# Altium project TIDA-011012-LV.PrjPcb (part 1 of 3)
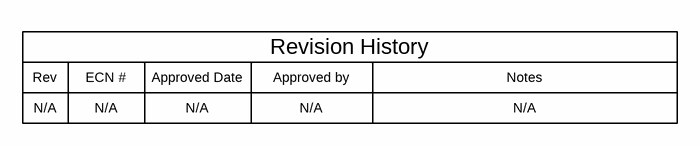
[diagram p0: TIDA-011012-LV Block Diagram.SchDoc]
CopyrightYear: 2026; EVM_orderable: NA; PCB_Rev: E1; PRJ_Customer: Public Release; PRJ_Engineer: A. Lechner, R. Ruffo; PRJ_Number: TIDA-011012-LV; PRJ_Title: Change in menu Project|Project Options|Parameters; SCH_Rev: E1; TechSupport: http://www.ti.com/support; TID: TIDA-011012-LV
10 sheets, 411 parts. Net scope: hierarchical (ports join the sheet entries above them; power ports are global).
Board file: TIDA-011012-LV.PcbDoc
Sheets:
  TIDA-011012-LV Block Diagram.SchDoc
  TIDA-011012-LV Power Conversion.SchDoc
    U_TIDA-011012 Fans and Temp Sense = TIDA-011012-LV Fans and Temp Sense.SchDoc
    U_TIDA-011012 Optical Interface = TIDA-011012-LV Optical Interface.SchDoc
    U_TIDA-011012 Communication = TIDA-011012-LV Communication.SchDoc
    U_TIDA-011012 DC IV Sensing = TIDA-011012-LV DC IV Sensing.SchDoc
    U_TIDA-011012 Current Comparator = TIDA-011012-LV Current Comparator.SchDoc
    U_TIDA-011012 Switch Node Hall Current Sensing = TIDA-011012-LV Switch Node Hall Current Sensing.SchDoc
    U_TIDA-011012 Auxiliary Power = TIDA-011012-LV  Auxiliary Power.SchDoc
    U_TIDA-011012_Hardware = TIDA-011012-LV Hardware.SchDoc

## Sheet TIDA-011012-LV Block Diagram.SchDoc
size 431 x 279 mm; Date: Not shown in title block; ApprovedBy: Not shown in title block; CheckedBy: Not shown in title block; Author: Not shown in title block; CompanyName: Not shown in title block; Engineer: Not shown in title block; Organization: Not shown in title block; Address1: Not shown in title block; Address2: Not shown in title block; Address3: Not shown in title block; Address4: Not shown in title block; DocumentNumber: 1; Revision: Use project parameter SCH_Rev; SheetNumber: 1; SheetTotal: 10; PageSetup: Record=PageOptions¦CenterHorizontal=True¦CenterVertical=True¦PrintScale=1.00¦XCorrection=1.00¦YCorrection=1.00¦PrintKind=0¦BorderSize=5000000¦LeftOffset=0¦BottomOffset=0¦Orientation=2¦PaperLength=1000¦PaperWidth=1000¦Scale=100¦PaperSource=15¦PrintQuality=600¦MediaType=1¦DitherType=10¦PaperKind=Letter¦PrintScaleMode=1

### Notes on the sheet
- Rev
- N/A
- ECN #
- Approved Date
- Approved by
- Revision History
- Notes

## Sheet TIDA-011012-LV Power Conversion.SchDoc
size 431 x 279 mm; Date: Not shown in title block; ApprovedBy: Not shown in title block; CheckedBy: Not shown in title block; Author: Not shown in title block; CompanyName: Not shown in title block; Engineer: Not shown in title block; Organization: Not shown in title block; Address1: Not shown in title block; Address2: Not shown in title block; Address3: Not shown in title block; Address4: Not shown in title block; DocumentNumber: 2; Revision: Use project parameter SCH_Rev; SheetNumber: 2; SheetTotal: 10; PageSetup: Record=PageOptions¦CenterHorizontal=True¦CenterVertical=True¦PrintScale=1.00¦XCorrection=1.00¦YCorrection=1.00¦PrintKind=0¦BorderSize=5000000¦LeftOffset=0¦BottomOffset=0¦Orientation=2¦PaperLength=1000¦PaperWidth=1000¦Scale=100¦PaperSource=15¦PrintQuality=600¦MediaType=1¦DitherType=10¦PaperKind=Letter¦PrintScaleMode=1
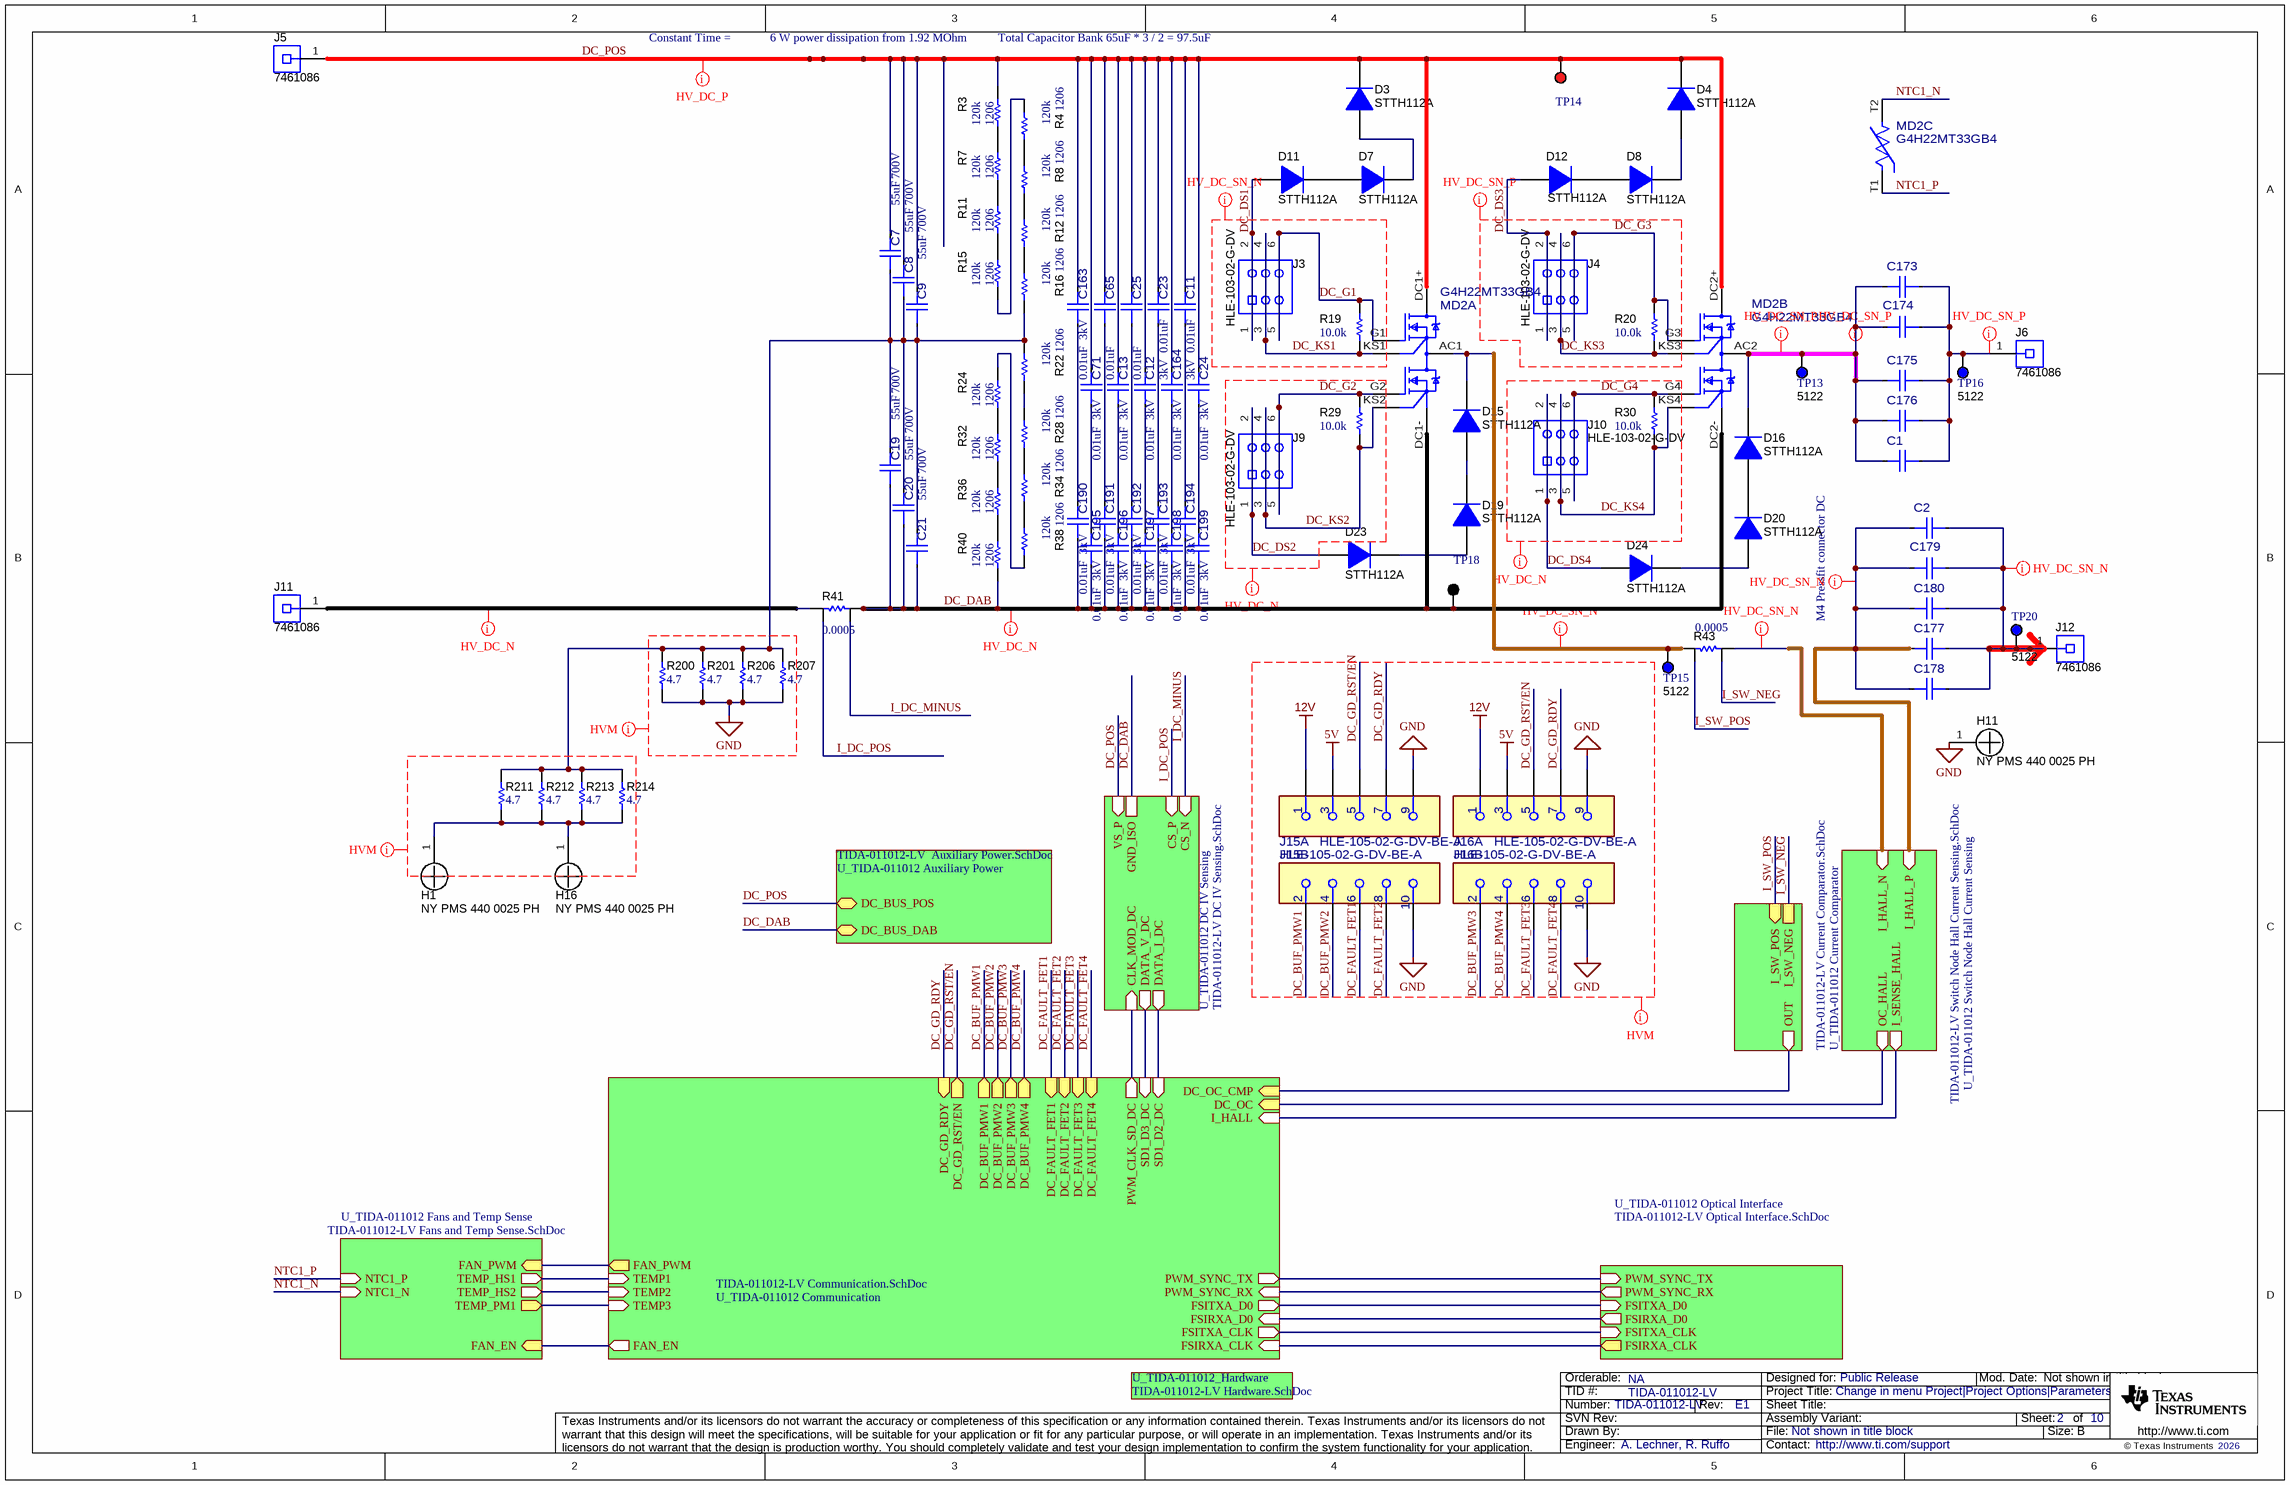
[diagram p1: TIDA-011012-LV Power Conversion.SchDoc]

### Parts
C1  C4ASMBW4200A3HJ  [FP-C4ASMBW4200A3HJ_RADIAL-MFG]  (value not drawn)
C2  C4ASMBW4200A3HJ  [FP-C4ASMBW4200A3HJ_RADIAL-MFG]  (value not drawn)
C7  ValueDisplayed: 55uF  VDC_V: 700V  [FP-C4AQJBW5550M3MJ_PTH_CAP_57MM5_30MM0-MFG]  (hidden comment: C4AQJBW5550M3MJ)
C8  ValueDisplayed: 55uF  VDC_V: 700V  [FP-C4AQJBW5550M3MJ_PTH_CAP_57MM5_30MM0-MFG]  (hidden comment: C4AQJBW5550M3MJ)
C9  ValueDisplayed: 55uF  VDC_V: 700V  [FP-C4AQJBW5550M3MJ_PTH_CAP_57MM5_30MM0-MFG]  (hidden comment: C4AQJBW5550M3MJ)
C11  ValueDisplayed: 0.01uF  VDC_V: 3kV  [FP-C2220X103KHRAC7800_2220-MFG]  (hidden comment: C2220X103KHRAC7800)
C12  ValueDisplayed: 0.01uF  VDC_V: 3kV  [FP-C2220X103KHRAC7800_2220-MFG]  (hidden comment: C2220X103KHRAC7800)
C13  ValueDisplayed: 0.01uF  VDC_V: 3kV  [FP-C2220X103KHRAC7800_2220-MFG]  (hidden comment: C2220X103KHRAC7800)
C19  ValueDisplayed: 55uF  VDC_V: 700V  [FP-C4AQJBW5550M3MJ_PTH_CAP_57MM5_30MM0-MFG]  (hidden comment: C4AQJBW5550M3MJ)
C20  ValueDisplayed: 55uF  VDC_V: 700V  [FP-C4AQJBW5550M3MJ_PTH_CAP_57MM5_30MM0-MFG]  (hidden comment: C4AQJBW5550M3MJ)
C21  ValueDisplayed: 55uF  VDC_V: 700V  [FP-C4AQJBW5550M3MJ_PTH_CAP_57MM5_30MM0-MFG]  (hidden comment: C4AQJBW5550M3MJ)
C23  ValueDisplayed: 0.01uF  VDC_V: 3kV  [FP-C2220X103KHRAC7800_2220-MFG]  (hidden comment: C2220X103KHRAC7800)
C24  ValueDisplayed: 0.01uF  VDC_V: 3kV  [FP-C2220X103KHRAC7800_2220-MFG]  (hidden comment: C2220X103KHRAC7800)
C25  ValueDisplayed: 0.01uF  [FP-C2220X103KHRAC7800_2220-MFG]  (hidden comment: C2220X103KHRAC7800)
C65  ValueDisplayed: 0.01uF  [FP-C2220X103KHRAC7800_2220-MFG]  (hidden comment: C2220X103KHRAC7800)
C71  ValueDisplayed: 0.01uF  VDC_V: 3kV  [FP-C2220X103KHRAC7800_2220-MFG]  (hidden comment: C2220X103KHRAC7800)
C163  ValueDisplayed: 0.01uF  VDC_V: 3kV  [FP-C2220X103KHRAC7800_2220-MFG]  (hidden comment: C2220X103KHRAC7800)
C164  ValueDisplayed: 0.01uF  VDC_V: 3kV  [FP-C2220X103KHRAC7800_2220-MFG]  (hidden comment: C2220X103KHRAC7800)
C173  C4ASMBW4200A3HJ  [FP-C4ASMBW4200A3HJ_RADIAL-MFG]  (value not drawn)
C174  C4ASMBW4200A3HJ  [FP-C4ASMBW4200A3HJ_RADIAL-MFG]  (value not drawn)
C175  C4ASMBW4200A3HJ  [FP-C4ASMBW4200A3HJ_RADIAL-MFG]  (value not drawn)
C176  C4ASMBW4200A3HJ  [FP-C4ASMBW4200A3HJ_RADIAL-MFG]  (value not drawn)
C177  C4ASMBW4200A3HJ  [FP-C4ASMBW4200A3HJ_RADIAL-MFG]  (value not drawn)
C178  C4ASMBW4200A3HJ  [FP-C4ASMBW4200A3HJ_RADIAL-MFG]  (value not drawn)
C179  C4ASMBW4200A3HJ  [FP-C4ASMBW4200A3HJ_RADIAL-MFG]  (value not drawn)
C180  C4ASMBW4200A3HJ  [FP-C4ASMBW4200A3HJ_RADIAL-MFG]  (value not drawn)
C190  ValueDisplayed: 0.01uF  VDC_V: 3kV  [FP-C2220X103KHRAC7800_2220-MFG]  (hidden comment: C2220X103KHRAC7800)
C191  ValueDisplayed: 0.01uF  VDC_V: 3kV  [FP-C2220X103KHRAC7800_2220-MFG]  (hidden comment: C2220X103KHRAC7800)
C192  ValueDisplayed: 0.01uF  VDC_V: 3kV  [FP-C2220X103KHRAC7800_2220-MFG]  (hidden comment: C2220X103KHRAC7800)
C193  ValueDisplayed: 0.01uF  VDC_V: 3kV  [FP-C2220X103KHRAC7800_2220-MFG]  (hidden comment: C2220X103KHRAC7800)
C194  ValueDisplayed: 0.01uF  VDC_V: 3kV  [FP-C2220X103KHRAC7800_2220-MFG]  (hidden comment: C2220X103KHRAC7800)
C195  ValueDisplayed: 0.01uF  VDC_V: 3kV  [FP-C2220X103KHRAC7800_2220-MFG]  (hidden comment: C2220X103KHRAC7800)
C196  ValueDisplayed: 0.01uF  VDC_V: 3kV  [FP-C2220X103KHRAC7800_2220-MFG]  (hidden comment: C2220X103KHRAC7800)
C197  ValueDisplayed: 0.01uF  VDC_V: 3kV  [FP-C2220X103KHRAC7800_2220-MFG]  (hidden comment: C2220X103KHRAC7800)
C198  ValueDisplayed: 0.01uF  VDC_V: 3kV  [FP-C2220X103KHRAC7800_2220-MFG]  (hidden comment: C2220X103KHRAC7800)
C199  ValueDisplayed: 0.01uF  VDC_V: 3kV  [FP-C2220X103KHRAC7800_2220-MFG]  (hidden comment: C2220X103KHRAC7800)
D3  STTH112A  [SMA]
D4  STTH112A  [SMA]
D7  STTH112A  [SMA]
D8  STTH112A  [SMA]
D11  STTH112A  [SMA]
D12  STTH112A  [SMA]
D15  STTH112A  [SMA]
D16  STTH112A  [SMA]
D19  STTH112A  [SMA]
D20  STTH112A  [SMA]
D23  STTH112A  [SMA]
D24  STTH112A  [SMA]
H1  NY PMS 440 0025 PH  [NY PMS 440 0025 PH]
H11  NY PMS 440 0025 PH  [NY PMS 440 0025 PH]
H16  NY PMS 440 0025 PH  [NY PMS 440 0025 PH]
J3  HLE-103-02-G-DV  [Samtec_HLE-103-02-x-DV]
J4  HLE-103-02-G-DV  [Samtec_HLE-103-02-x-DV]
J5  7461086  [Wurth_7461086]
J6  7461086  [Wurth_7461086]
J9  HLE-103-02-G-DV  [Samtec_HLE-103-02-x-DV]
J10  HLE-103-02-G-DV  [Samtec_HLE-103-02-x-DV]
J11  7461086  [Wurth_7461086]
J12  7461086  [Wurth_7461086]
J15  HLE-105-02-G-DV-BE-A  [FP-HLE-105-02-G-DV-BE-A_CONN_RCPT_10-MFG]  (parts A,B of 2)
J16  HLE-105-02-G-DV-BE-A  [FP-HLE-105-02-G-DV-BE-A_CONN_RCPT_10-MFG]  (parts A,B of 2)
MD2  G4H22MT33GB4  [FP-G4H22MT33GB4_SiCPAK-G+_MODIFIED-MFG]  (parts A,B,C of 3)
R3  ValueDisplayed: 120k  [1206]  (hidden comment: RC1206FR-07120KL)
R4  ValueDisplayed: 120k  [1206]  (hidden comment: RC1206FR-07120KL)
R7  ValueDisplayed: 120k  [1206]  (hidden comment: RC1206FR-07120KL)
R8  ValueDisplayed: 120k  [1206]  (hidden comment: RC1206FR-07120KL)
R11  ValueDisplayed: 120k  [1206]  (hidden comment: RC1206FR-07120KL)
R12  ValueDisplayed: 120k  [1206]  (hidden comment: RC1206FR-07120KL)
R15  ValueDisplayed: 120k  [1206]  (hidden comment: RC1206FR-07120KL)
R16  ValueDisplayed: 120k  [1206]  (hidden comment: RC1206FR-07120KL)
R19  ValueDisplayed: 10.0k  [0603]  (hidden comment: ERJ-3EKF1002V)
R20  ValueDisplayed: 10.0k  [0603]  (hidden comment: ERJ-3EKF1002V)
R22  ValueDisplayed: 120k  [1206]  (hidden comment: RC1206FR-07120KL)
R24  ValueDisplayed: 120k  [1206]  (hidden comment: RC1206FR-07120KL)
R28  ValueDisplayed: 120k  [1206]  (hidden comment: RC1206FR-07120KL)
R29  ValueDisplayed: 10.0k  [0603]  (hidden comment: ERJ-3EKF1002V)
R30  ValueDisplayed: 10.0k  [0603]  (hidden comment: ERJ-3EKF1002V)
R32  ValueDisplayed: 120k  [1206]  (hidden comment: RC1206FR-07120KL)
R34  ValueDisplayed: 120k  [1206]  (hidden comment: RC1206FR-07120KL)
R36  ValueDisplayed: 120k  [1206]  (hidden comment: RC1206FR-07120KL)
R38  ValueDisplayed: 120k  [1206]  (hidden comment: RC1206FR-07120KL)
R40  ValueDisplayed: 120k  [1206]  (hidden comment: RC1206FR-07120KL)
R41  ValueDisplayed: 0.0005  [WSL4026_0p5milli]  (hidden comment: WSL4026L5000FEB)
R43  ValueDisplayed: 0.0005  [WSL4026_0p5milli]  (hidden comment: WSL4026L5000FEB)
R200  ValueDisplayed: 4.7  [1206]  (hidden comment: CRCW12064R70JNEA)
R201  ValueDisplayed: 4.7  [1206]  (hidden comment: CRCW12064R70JNEA)
R206  ValueDisplayed: 4.7  [1206]  (hidden comment: CRCW12064R70JNEA)
R207  ValueDisplayed: 4.7  [1206]  (hidden comment: CRCW12064R70JNEA)
R211  ValueDisplayed: 4.7  [1206]  (hidden comment: CRCW12064R70JNEA)
R212  ValueDisplayed: 4.7  [1206]  (hidden comment: CRCW12064R70JNEA)
R213  ValueDisplayed: 4.7  [1206]  (hidden comment: CRCW12064R70JNEA)
R214  ValueDisplayed: 4.7  [1206]  (hidden comment: CRCW12064R70JNEA)
TP13  5122  [Keystone5122]
TP14  5010  [Keystone5010]  (value not drawn)
TP15  5122  [Keystone5122]
TP16  5122  [Keystone5122]
TP18  5011  [Keystone5011]  (value not drawn)
TP20  5122  [Keystone5122]

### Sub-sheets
U_TIDA-011012 Auxiliary Power = TIDA-011012-LV  Auxiliary Power.SchDoc: DC_BUS_POS (bidir), DC_BUS_DAB (bidir)
U_TIDA-011012 Communication = TIDA-011012-LV Communication.SchDoc: SD1_D2_DC (in), SD1_D3_DC (in), FAN_EN (out), TEMP1 (in), TEMP2 (in), TEMP3 (in), FSITXA_D0 (out), PWM_SYNC_TX (out), PWM_SYNC_RX (in), I_HALL (in), PWM_CLK_SD_DC (out), DC_GD_RDY (in), DC_FAULT_FET1 (in), DC_OC (in), DC_OC_CMP (in), DC_BUF_PMW1 (out), DC_BUF_PMW2 (out), DC_BUF_PMW3 (out), DC_BUF_PMW4 (out), DC_FAULT_FET2 (in), DC_FAULT_FET3 (in), DC_FAULT_FET4 (in), DC_GD_RST/EN (out), FAN_PWM (out), FSIRXA_D0 (in), FSITXA_CLK (out), FSIRXA_CLK (in)
U_TIDA-011012 Current Comparator = TIDA-011012-LV Current Comparator.SchDoc: OUT (out), I_SW_NEG, I_SW_POS (in)
U_TIDA-011012 DC IV Sensing = TIDA-011012-LV DC IV Sensing.SchDoc: CS_P (in), CS_N (in), DATA_I_DC (out), GND_ISO, VS_P (in), DATA_V_DC (out), CLK_MOD_DC (in)
U_TIDA-011012 Fans and Temp Sense = TIDA-011012-LV Fans and Temp Sense.SchDoc: TEMP_HS1 (out), TEMP_HS2 (out), NTC1_P (in), NTC1_N (in), FAN_EN (in), FAN_PWM (in), TEMP_PM1 (out)
U_TIDA-011012 Optical Interface = TIDA-011012-LV Optical Interface.SchDoc: PWM_SYNC_RX (out), FSITXA_D0 (in), PWM_SYNC_TX (in), FSITXA_CLK (in), FSIRXA_D0 (out), FSIRXA_CLK (out)
U_TIDA-011012 Switch Node Hall Current Sensing = TIDA-011012-LV Switch Node Hall Current Sensing.SchDoc: I_HALL_P (in), I_HALL_N (in), I_SENSE_HALL (out), OC_HALL (out)
U_TIDA-011012_Hardware = TIDA-011012-LV Hardware.SchDoc: no entries

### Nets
5V: J15.3 J16.3
12V: J15.1 J16.1
GND: H11.1 J15.9 J15.10 J16.9 J16.10 R200.1 R201.1 R206.1 R207.1
CLK_MOD_DC: sheet U_TIDA-011012 Communication/PWM_CLK_SD_DC, sheet U_TIDA-011012 DC IV Sensing/CLK_MOD_DC
DATA_I_DC: sheet U_TIDA-011012 Communication/SD1_D2_DC, sheet U_TIDA-011012 DC IV Sensing/DATA_I_DC
DATA_V_DC: sheet U_TIDA-011012 Communication/SD1_D3_DC, sheet U_TIDA-011012 DC IV Sensing/DATA_V_DC
DC_BUF_PMW1: J15.2 ; sheet U_TIDA-011012 Communication/DC_BUF_PMW1
DC_BUF_PMW2: J15.4 ; sheet U_TIDA-011012 Communication/DC_BUF_PMW2
DC_BUF_PMW3: J16.2 ; sheet U_TIDA-011012 Communication/DC_BUF_PMW3
DC_BUF_PMW4: J16.4 ; sheet U_TIDA-011012 Communication/DC_BUF_PMW4
DC_DAB: C19.1 C20.1 C21.1 C190.1 C191.1 C192.1 C193.1 C194.1 C195.1 C196.1 C197.1 C198.1 C199.1 MD2.DC1- MD2.DC2- R40.1 R41.2 TP18.1 ; sheet U_TIDA-011012 DC IV Sensing/GND_ISO, sheet U_TIDA-011012 Auxiliary Power/DC_BUS_DAB
DC_DS1: D11.2(A) J3.1 J3.2
DC_DS2: D23.2(A) J9.1 J9.2
DC_DS3: D12.2(A) J4.1 J4.2
DC_DS4: D24.2(A) J10.1 J10.2
DC_FAULT_FET1: J15.6 ; sheet U_TIDA-011012 Communication/DC_FAULT_FET1
DC_FAULT_FET2: J15.8 ; sheet U_TIDA-011012 Communication/DC_FAULT_FET2
DC_FAULT_FET3: J16.6 ; sheet U_TIDA-011012 Communication/DC_FAULT_FET3
DC_FAULT_FET4: J16.8 ; sheet U_TIDA-011012 Communication/DC_FAULT_FET4
DC_G1: J3.5 J3.6 MD2.G1 R19.2
DC_G2: J9.5 J9.6 MD2.G2 R29.2
DC_G3: J4.5 J4.6 MD2.G3 R20.2
DC_G4: J10.5 J10.6 MD2.G4 R30.2
DC_GD_RDY: J15.7 J16.7 ; sheet U_TIDA-011012 Communication/DC_GD_RDY
DC_GD_RST/EN: J15.5 J16.5 ; sheet U_TIDA-011012 Communication/DC_GD_RST/EN
DC_KS1: J3.3 J3.4 MD2.KS1 R19.1
DC_KS2: J9.3 J9.4 MD2.KS2 R29.1
DC_KS3: J4.3 J4.4 MD2.KS3 R20.1
DC_KS4: J10.3 J10.4 MD2.KS4 R30.1
DC_OC: sheet U_TIDA-011012 Communication/DC_OC, sheet U_TIDA-011012 Switch Node Hall Current Sensing/OC_HALL
DC_OC_CMP: sheet U_TIDA-011012 Communication/DC_OC_CMP, sheet U_TIDA-011012 Current Comparator/OUT
DC_POS: C7.2 C8.2 C9.2 C11.2 C12.2 C13.2 C23.2 C24.2 C25.2 C65.2 C71.2 C163.2 C164.2 D3.1(K) D4.1(K) J5.1 MD2.DC1+ MD2.DC2+ R3.2 TP14.1 ; sheet U_TIDA-011012 DC IV Sensing/VS_P, sheet U_TIDA-011012 Auxiliary Power/DC_BUS_POS
FAN_EN: sheet U_TIDA-011012 Fans and Temp Sense/FAN_EN, sheet U_TIDA-011012 Communication/FAN_EN
FAN_PWM: sheet U_TIDA-011012 Fans and Temp Sense/FAN_PWM, sheet U_TIDA-011012 Communication/FAN_PWM
FSIRXA_CLK: sheet U_TIDA-011012 Optical Interface/FSIRXA_CLK, sheet U_TIDA-011012 Communication/FSIRXA_CLK
FSIRXA_D0: sheet U_TIDA-011012 Optical Interface/FSIRXA_D0, sheet U_TIDA-011012 Communication/FSIRXA_D0
FSITXA_CLK: sheet U_TIDA-011012 Optical Interface/FSITXA_CLK, sheet U_TIDA-011012 Communication/FSITXA_CLK
FSITXA_D0: sheet U_TIDA-011012 Optical Interface/FSITXA_D0, sheet U_TIDA-011012 Communication/FSITXA_D0
I_DC_MINUS: R41.4 ; sheet U_TIDA-011012 DC IV Sensing/CS_N
I_DC_POS: R41.3 ; sheet U_TIDA-011012 DC IV Sensing/CS_P
I_HALL: sheet U_TIDA-011012 Communication/I_HALL, sheet U_TIDA-011012 Switch Node Hall Current Sensing/I_SENSE_HALL
I_HALL_N: R43.2 ; sheet U_TIDA-011012 Switch Node Hall Current Sensing/I_HALL_N
I_HALL_P: C2.2 C177.2 C178.2 C179.2 C180.2 ; sheet U_TIDA-011012 Switch Node Hall Current Sensing/I_HALL_P
I_SW_NEG: R43.4 ; sheet U_TIDA-011012 Current Comparator/I_SW_NEG
I_SW_POS: R43.3 ; sheet U_TIDA-011012 Current Comparator/I_SW_POS
NTC1_N: MD2.T2 ; sheet U_TIDA-011012 Fans and Temp Sense/NTC1_N
NTC1_P: MD2.T1 ; sheet U_TIDA-011012 Fans and Temp Sense/NTC1_P
PWM_SYNC_RX: sheet U_TIDA-011012 Optical Interface/PWM_SYNC_RX, sheet U_TIDA-011012 Communication/PWM_SYNC_RX
PWM_SYNC_TX: sheet U_TIDA-011012 Optical Interface/PWM_SYNC_TX, sheet U_TIDA-011012 Communication/PWM_SYNC_TX
TEMP1: sheet U_TIDA-011012 Fans and Temp Sense/TEMP_HS1, sheet U_TIDA-011012 Communication/TEMP1
TEMP2: sheet U_TIDA-011012 Fans and Temp Sense/TEMP_HS2, sheet U_TIDA-011012 Communication/TEMP2
TEMP3: sheet U_TIDA-011012 Fans and Temp Sense/TEMP_PM1, sheet U_TIDA-011012 Communication/TEMP3
NetC1_1: C1.1 C173.1 C174.1 C175.1 C176.1 J6.1 TP16.1
NetC1_2: C1.2 C173.2 C174.2 C175.2 C176.2 D16.1(K) MD2.AC2 TP13.1
NetC2_1: C2.1 C177.1 C178.1 C179.1 C180.1 J12.1 TP20.1
NetC7_1: C7.1 C8.1 C9.1 C19.2 C20.2 C21.2 R16.2 R22.1 R200.2 R201.2 R206.2 R207.2 R211.2 R212.2 R213.2 R214.2
NetC11_1: C11.1 C194.2
NetC12_1: C12.1 C197.2
NetC13_1: C13.1 C196.2
NetC23_1: C23.1 C193.2
NetC24_1: C24.1 C199.2
NetC25_1: C25.1 C192.2
NetC65_1: C65.1 C191.2
NetC71_1: C71.1 C195.2
NetC163_1: C163.1 C190.2
NetC164_1: C164.1 C198.2
NetD3_2: D3.2(A) D7.1(K)
NetD4_2: D4.2(A) D8.1(K)
NetD7_2: D7.2(A) D11.1(K)
NetD8_2: D8.2(A) D12.1(K)
NetD15_1: D15.1(K) MD2.AC1 R43.1 TP15.1
NetD15_2: D15.2(A) D19.1(K)
NetD16_2: D16.2(A) D20.1(K)
NetD19_2: D19.2(A) D23.1(K)
NetD20_2: D20.2(A) D24.1(K)
NetH1_1: H1.1 H16.1 R211.1 R212.1 R213.1 R214.1
NetJ11_1: J11.1 R41.1
NetR3_1: R3.1 R7.2
NetR4_1: R4.1 R15.1
NetR4_2: R4.2 R8.1
NetR7_1: R7.1 R11.2
NetR8_2: R8.2 R12.1
NetR11_1: R11.1 R15.2
NetR12_2: R12.2 R16.1
NetR22_2: R22.2 R28.1
NetR24_1: R24.1 R32.2
NetR24_2: R24.2 R38.2
NetR28_2: R28.2 R34.1
NetR32_1: R32.1 R36.2
NetR34_2: R34.2 R38.1
NetR36_1: R36.1 R40.2

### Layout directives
net class HV_DC_N: DC_DAB, DC_DS2, DC_G2, DC_G4, DC_KS2, DC_KS4, NetJ11_1
net class HV_DC_SN_N: DC_DS1, DC_G1, DC_KS1, I_HALL_N, I_HALL_P, NetC2_1, NetD15_1
net class HV_DC_SN_P: DC_DS3, DC_G3, DC_KS3, NetC1_1, NetC1_2
net class HVM: 5V, 12V, (no net found under the mark), DC_BUF_PMW1, DC_BUF_PMW2, DC_BUF_PMW3, DC_BUF_PMW4, DC_FAULT_FET1, DC_FAULT_FET2, DC_FAULT_FET3, DC_FAULT_FET4, DC_GD_RDY, DC_GD_RST/EN, GND
net class HV_DC_P: DC_POS

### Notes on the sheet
- Constant Time =
- 6 W power dissipation from 1.92 MOhm
- Total Capacitor Bank 65uF * 3 / 2 = 97.5uF
- M4 Pressfit connector DC

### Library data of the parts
C1 C2 C173-C180 = CMP-0128991-1: 2 µF Film Capacitor 500V 850V Polypropylene (PP), Metallized Radial - 4 Leads; Manufacturer: KEMET; AEC Qualified: No; Cap_F: 2µF; SizeZ_mm: 44mm; Tolerance_%: 5%; ValueDisplayed: 2uF; Value: 2µF
C7-C9 C19-C21 = CMP-0128990-1: 55 µF Film Capacitor 700V Polypropylene (PP), Metallized Radial - 4 Leads; Manufacturer: KEMET; AEC Grade: Grade 2; AEC Qualified: Yes; Cap_F: 55µF; SizeZ_mm: 45.3mm; Tolerance_%: 5%; Standoff Height: 0.5mm; Value: 55µF
C11-C13 C23-C25 C65 C71 C163 C164 C190-C199 = CMP-0128868-1: 10000 pF ±10% 3000V (3kV) Ceramic Capacitor X7R 2220 (5750 Metric); Manufacturer: KEMET; AEC Grade: NA; AEC Qualified: No; Cap_F: 10nF; SizeZ_mm: 2.2mm; TempCo: 15%; Value: 10nF
D3 D4 D7 D8 D11 D12 D15 D16 D19 D20 D23 D24 = CMP-0077081-2: Diode, Ultrafast, 1200 V, 1 A, SMA; Manufacturer: STMicroelectronics; AEC Qualified: N; TJmax_C: 175°C; SizeX_mm: 5.59; Green_Lifecycle: Not Set; Io_A: 1A; Value2: 1.9V; SizeY_mm: 2.92; SizeZ_mm: 2.87; AEC Category: Q101; Value: 1200V; SizeAreaWB_mm2: 37.3428; Vr_V: 1.2kV; Green_REACh: Incomplete; SizeArea_mm2: 16.3228
H1 H11 H16 = CMP-0003617-1: Machine Screw, Round, #4-40 x 1/4, Nylon, Philips panhead; Manufacturer: B&F Fastener Supply; CompType: Hardware
J3 J4 J9 J10 = CMP-0082272-1: Receptacle, 2.54mm, 3x2, Gold, SMT; Manufacturer: Samtec; Pitch_mm: 2.54; Gender: Female; Cert_UL: Y; Voltage_V: 400V; Current_A: 4.1A; Row_Count: 2; CompType: Socket Strip
J5 J6 J11 J12 = CMP-0054757-1: Power Element Bush, M4, 12, TH; Manufacturer: Wurth Elektronik; CNHeader: FALSE; Gender: Female; CompType: Screw Terminal; Pitch_mm: 2.54
J15 J16 = CMP-0127514-1: Conn Socket Strip SKT 10 POS 2.54mm Solder ST Top Entry SMD Tube; Manufacturer: Samtec; ContactFinish: Gold,Nickel; Current_A: 4.1A; Row_Count: 2; Voltage_V: 566V; AEC Grade: NA; AEC Qualified: No; Conn Gender: Female; Conn Orientation: Vertical; Is Female: yes; SizeZ_mm: 3.79mm
MD2 = CMP-0128745-2: 3300V 22.5mΩ Full-Bridge / Dual-Half-Bridge SiC Module; Manufacturer: Navitas Semiconductor; AEC Qualified: No; IdsMax_A: 105A; QgTyp_nC: 590nC @ 18V; Rdson45_ohm: 22.5m; SizeZ_mm: 12.9mm; VdsMax_V: 3.3kV; Vgs_V: 18V; Input Capacitance At Vds: 13820pF @ 2000V; Threshold Vgs Max: 4.3V; Threshold Vgs Min: 2.5V; TJmax_C: +175°C; Typ Forward Diode Voltage: 4V; ChMode: Enhancement
R3 R4 R7 R8 R11 R12 R15 R16 R22 R24 R28 R32 R34 R36 R38 R40 = CMP-0017868-2: RES, 120 k, 1%, 0.25 W, 1206; Manufacturer: Yageo America; Power_W: 250mW; TempCo: 100 ppm/C; U/M: EA; Value: 120k; SizeX_mm: 3.2; SizeY_mm: 1.6; SizeZ_mm: 1.35; Value2: 0.25W; SizeArea_mm2: 5.12; VDC_V: 200V; AEC Category: Q200
R19 R20 R29 R30 = CMP-0022684-3: RES, 10.0 k, 1%, 0.1 W, 0603; Manufacturer: Panasonic; Power_W: 100mW; TempCo: 100 ppm/C; Value_Code: 10k0; U/M: EA; Value: 10.0k; EIA_Code: E96; Res_ohm: 10k; SizeX_mm: 1.6; SizeY_mm: 0.8; SizeZ_mm: 1; Value2: 0.1W; SizeArea_mm2: 1.28; VDC_V: 75V; AEC Category: Q200
R41 R43 = CMP-0065757-2: RES, 0.0005, 1%, 3 W, 4026; Manufacturer: Vishay-Dale; Power_W: 3W; TempCo: 75 ppm/C; Value_Code: L5000; U/M: EA; Value: 0.0005; Res_ohm: 500µ; CompType: Resistor; AEC Qualified: N; AEC Category: Q200
R200 R201 R206 R207 R211-R214 = CMP-0018693-3: RES, 4.7, 5%, 0.25 W, AEC-Q200 Grade 0, 1206; Manufacturer: Vishay-Dale; Power_W: 250mW; TempCo: 200 ppm/C; Value_Code: 4R70; Value: 4.7; EIA_Code: E24; SizeX_mm: 3.2; SizeY_mm: 1.6; SizeZ_mm: 1.35; Value2: 0.25W; SizeArea_mm2: 5.12; AEC Qualified: Y; VDC_V: 200V; AEC Category: Q200; AEC Grade: 0
TP13 TP15 TP16 TP20 = CMP-0055155-2: Test Point, Compact, Blue, TH; Manufacturer: Keystone Electronics; Green_Lifecycle: Active; CNHeader: FALSE; ContactFinish: Silver; CT: TRUE; Green_REACh: Passed
TP14 = CMP-0055147-2: Test Point, Multipurpose, Red, TH; Manufacturer: Keystone Electronics; CT: TRUE; ContactFinish: Silver; Green_Lifecycle: Active; CNHeader: FALSE; Green_REACh: Passed
TP18 = CMP-0055148-2: Test Point, Multipurpose, Black, TH; Manufacturer: Keystone Electronics; CNHeader: FALSE; ContactFinish: Silver; Green_REACh: Passed; Green_Lifecycle: Active; CT: TRUE

## Sheet TIDA-011012-LV Fans and Temp Sense.SchDoc
size 431 x 279 mm; Date: Not shown in title block; ApprovedBy: Not shown in title block; CheckedBy: Not shown in title block; Author: Not shown in title block; CompanyName: Not shown in title block; Engineer: Not shown in title block; Organization: Not shown in title block; Address1: Not shown in title block; Address2: Not shown in title block; Address3: Not shown in title block; Address4: Not shown in title block; DocumentNumber: 7; Revision: Use project parameter SCH_Rev; SheetNumber: 7; SheetTotal: 10; PageSetup: Record=PageOptions¦CenterHorizontal=True¦CenterVertical=True¦PrintScale=1.00¦XCorrection=1.00¦YCorrection=1.00¦PrintKind=0¦BorderSize=5000000¦LeftOffset=0¦BottomOffset=0¦Orientation=2¦PaperLength=1000¦PaperWidth=1000¦Scale=100¦PaperSource=15¦PrintQuality=600¦MediaType=1¦DitherType=10¦PaperKind=Letter¦PrintScaleMode=1
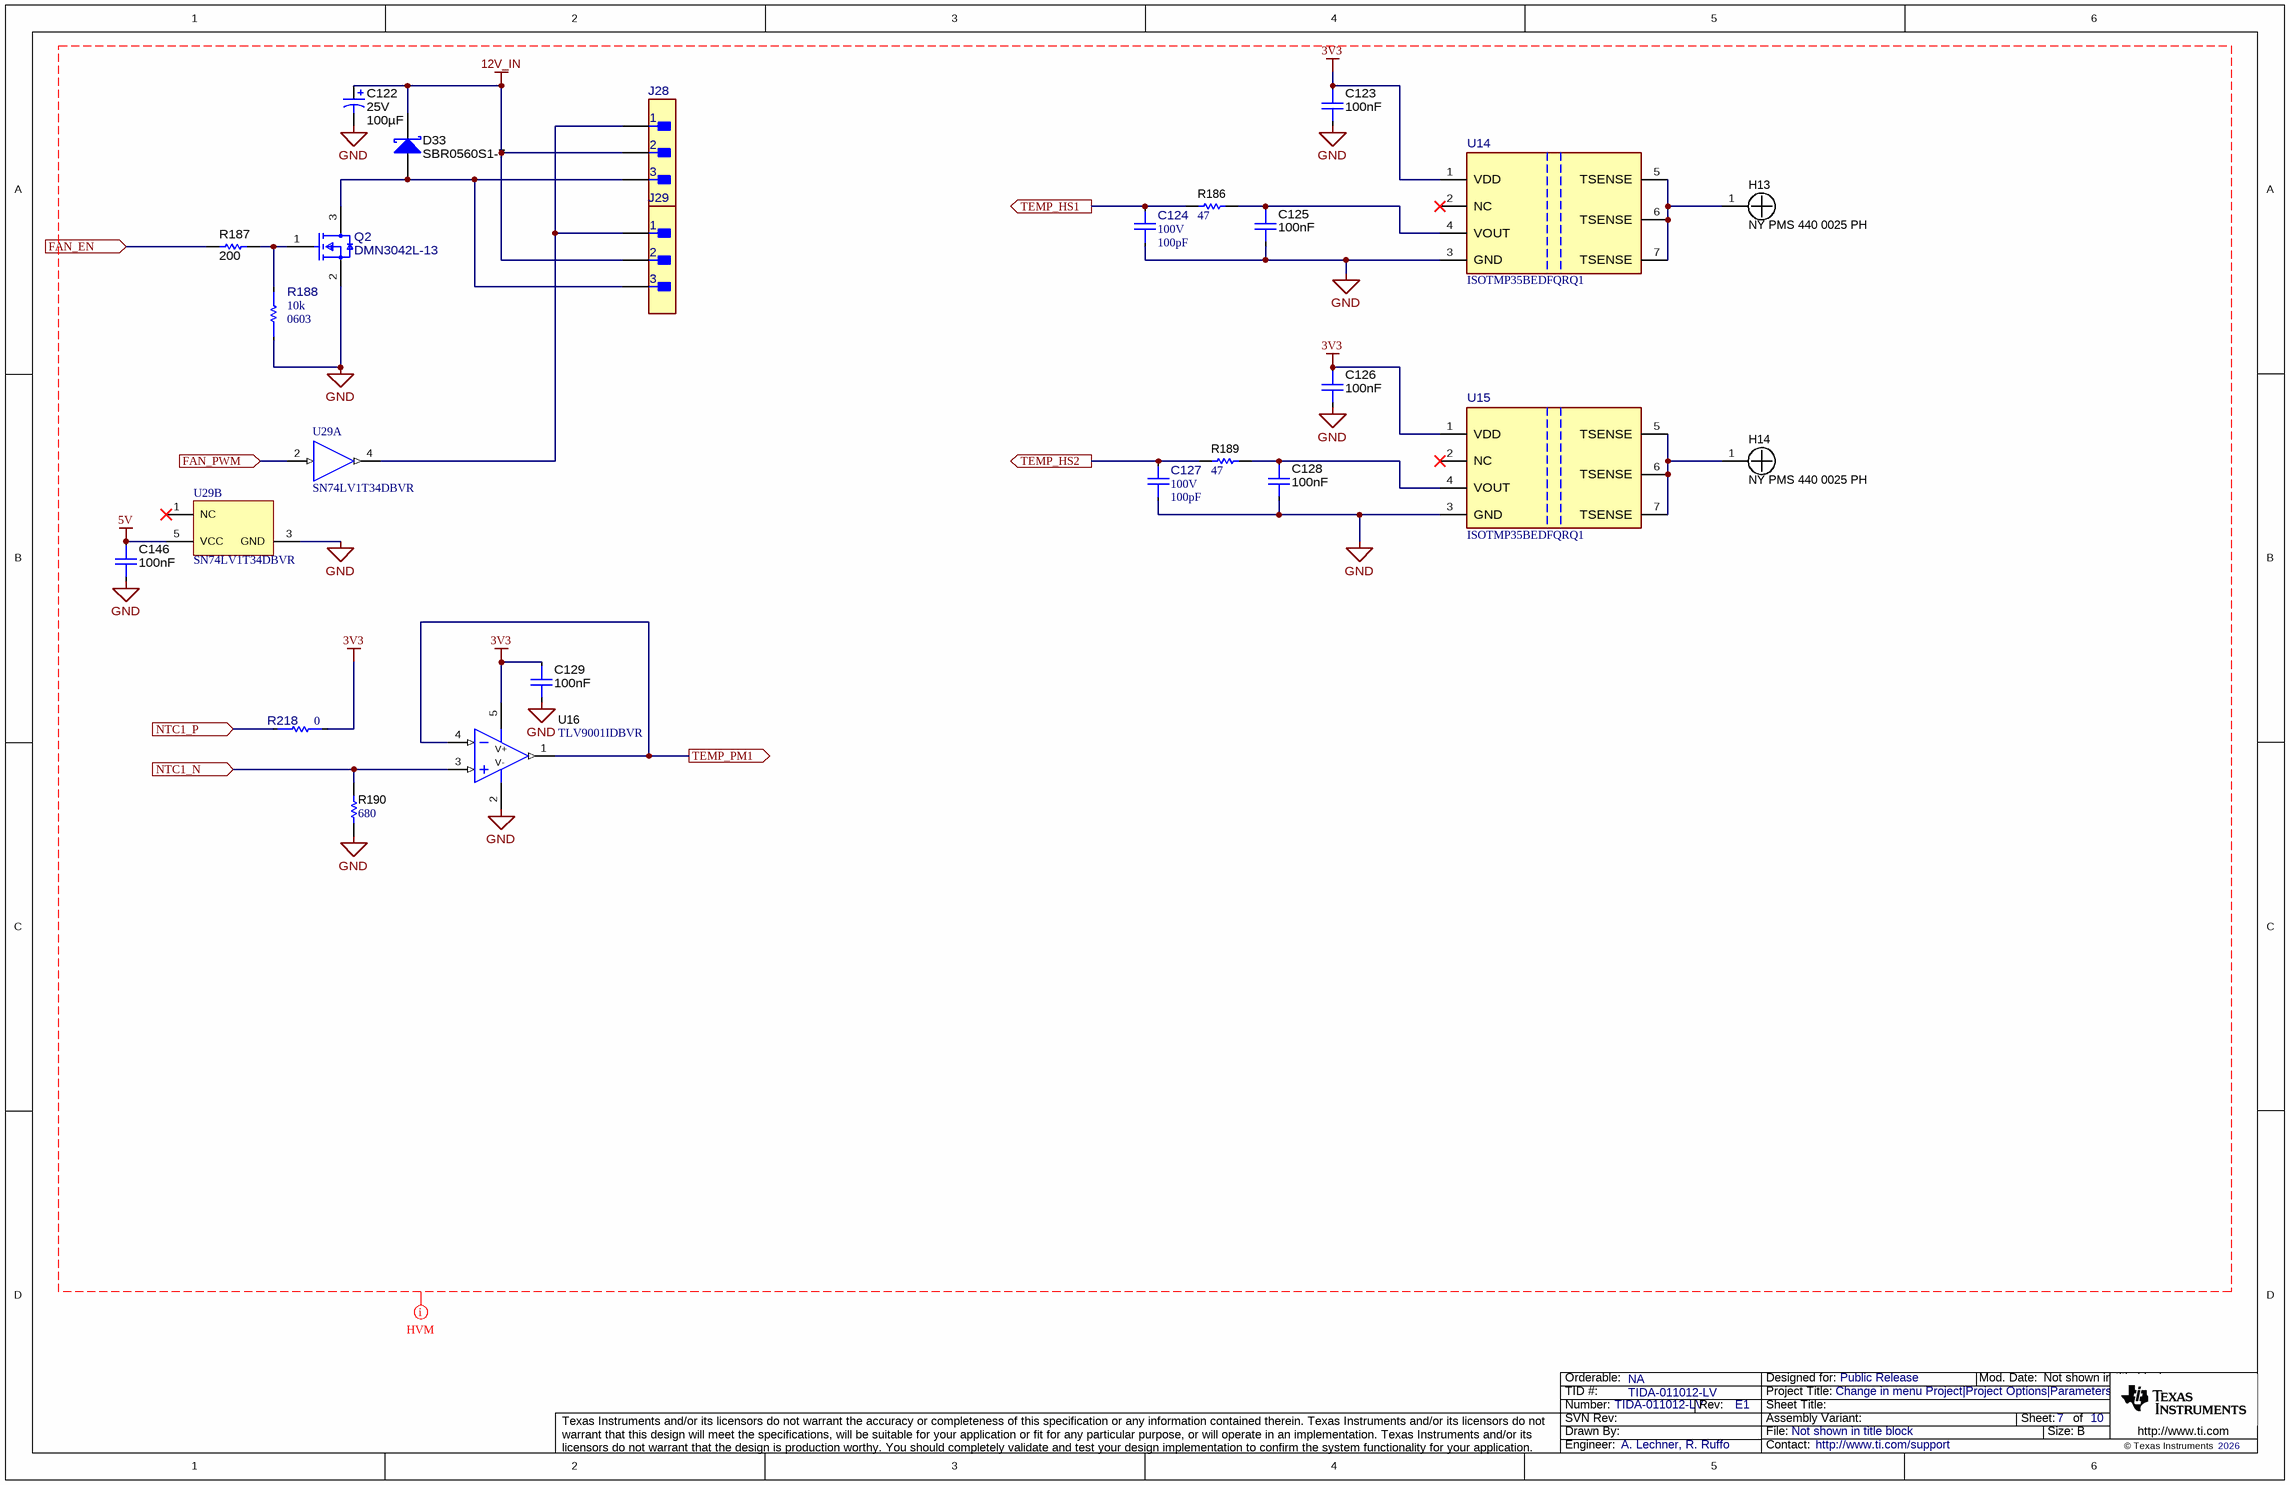
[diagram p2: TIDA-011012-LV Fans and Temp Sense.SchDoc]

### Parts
C122  VDC_V: 25V  ValueDisplayed: 100µF  [UWT_630x770]  (hidden comment: UWT1E101MCL1GS)
C123  Cap_F: 100nF  [FP-CL10B104KA8VPJC_0603-MFG]  (hidden comment: CL10B104KA8VPJC)
C124  VDC_V: 100V  Cap_F: 100pF  [FP-06031C101JAT2A_0603-MFG]  (hidden comment: 06031C101JAT2A)
C125  Cap_F: 100nF  [FP-CL10B104KA8VPJC_0603-MFG]  (hidden comment: CL10B104KA8VPJC)
C126  Cap_F: 100nF  [FP-CL10B104KA8VPJC_0603-MFG]  (hidden comment: CL10B104KA8VPJC)
C127  VDC_V: 100V  Cap_F: 100pF  [FP-06031C101JAT2A_0603-MFG]  (hidden comment: 06031C101JAT2A)
C128  Cap_F: 100nF  [FP-CL10B104KA8VPJC_0603-MFG]  (hidden comment: CL10B104KA8VPJC)
C129  Cap_F: 100nF  [FP-CL10B104KA8VPJC_0603-MFG]  (hidden comment: CL10B104KA8VPJC)
C146  Cap_F: 100nF  [FP-CL10B104KA8VPJC_0603-MFG]  (hidden comment: CL10B104KA8VPJC)
D33  SBR0560S1-7  [SOD-123]
H13  NY PMS 440 0025 PH  [NY PMS 440 0025 PH]
H14  NY PMS 440 0025 PH  [NY PMS 440 0025 PH]
J28  0022111031  [FP-0022111031_HDR3-MFG]  (value not drawn)
J29  0022111031  [FP-0022111031_HDR3-MFG]  (value not drawn)
Q2  DMN3042L-13  [FP-DMN3042L-13_SOT23-MFG]
R186  ValueDisplayed: 47  [0603]  (hidden comment: ERJ-3GEYJ470V)
R187  ValueDisplayed: 200  [0603]  (hidden comment: RT0603BRD07200RL)
R188  PackageReference: 0603  Res_ohm: 10k  [FP-CRCW060310K0JNEBC_0603-MFG]  (hidden comment: CRCW060310K0JNEBC)
R189  ValueDisplayed: 47  [0603]  (hidden comment: ERJ-3GEYJ470V)
R190  ValueDisplayed: 680  [0603]  (hidden comment: RC0603FR-07680RL)
R218  value 0  [FP-ERJ-H3G0R00V_0603-MFG]  (hidden comment: ERJ-H3G0R00V)
U14  ISOTMP35BEDFQRQ1  [DFQ0007A-MFG]
U15  ISOTMP35BEDFQRQ1  [DFQ0007A-MFG]
U16  TLV9001IDBVR  [DBV0005A_N]
U29  SN74LV1T34DBVR  [DBV0005A_N]  (parts A,B of 2)

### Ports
FAN_EN (in), FAN_PWM (in), NTC1_N (in), NTC1_P (in), TEMP_HS1 (out), TEMP_HS2 (out), TEMP_PM1 (out)

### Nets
3V3: C123.1 C126.1 C129.1 R218.2 U14.1(VDD) U15.1(VDD) U16.5(V+)
5V: C146.1 U29.5(VCC)
12V_IN: C122.1(+) D33.1(K) J28.2 J29.2
GND: C122.2(-) C123.2 C124.1 C125.2 C126.2 C127.1 C128.2 C129.2 C146.2 Q2.2(S) R188.1 R190.1 U14.3(GND) U15.3(GND) U16.2(V-) U29.3(GND)
FAN_EN: R187.1 ; port FAN_EN
FAN_PWM: U29.2(A) ; port FAN_PWM
NTC1_N: R190.2 U16.3(IN+) ; port NTC1_N
NTC1_P: R218.1 ; port NTC1_P
TEMP1: C124.2 R186.1 ; port TEMP_HS1
TEMP2: C127.2 R189.1 ; port TEMP_HS2
TEMP3: U16.1(OUT) U16.4(IN-) ; port TEMP_PM1
NetC125_1: C125.1 R186.2 U14.4(VOUT)
NetC128_1: C128.1 R189.2 U15.4(VOUT)
NetD33_2: D33.2(A) J28.3 J29.3 Q2.3(D)
NetH13_1: H13.1 U14.5(TSENSE) U14.6(TSENSE) U14.7(TSENSE)
NetH14_1: H14.1 U15.5(TSENSE) U15.6(TSENSE) U15.7(TSENSE)
NetJ28_1: J28.1 J29.1 U29.4(Y)
NetQ2_1: Q2.1(G) R187.2 R188.2

Not connected (* = marked no-connect by the designer): U14 2(NC)*; U15 2(NC)*; U29 1(NC)*

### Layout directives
net class HVM: 3V3, 5V, 12V_IN, GND

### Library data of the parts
C122 = CMP-0081462-1: CAP, AL, 100 µF, 25 V, +/- 20%, SMD; Manufacturer: Nichicon; TaMin_C: -55°C; Polarized: Y; SizeAreaWB_mm2: 77.4; U/M: EA; Value: 100uF; TaMax_C: 105°C; SizeZ_mm: 8; SizeX_mm: 7; SizeY_mm: 6.6; Cap_Case: 6.3x7.7mm; SizeArea_mm2: 46.2; CompType: Capacitor; AEC Qualified: N; IRMS_A: 91mA; AEC Category: Q200
C123 C125 C126 C128 C129 C146 = CMP-0121051-1: Automotive CAP, 100㎋, 25V, ±10%, X7R, 0603, 5mm Bending; Manufacturer: Samsung; AEC Grade: Grade 1; AEC Qualified: Yes; SizeZ_mm: 0.9mm; TempCo: 15%; Value: 100nF
C124 C127 = CMP-0096605-1: 100 pF ±5% 100V Ceramic Capacitor X7R 0603 (1608 Metric); Manufacturer: KYOCERA AVX; TempCo: 15%; AEC Qualified: No; SizeZ_mm: 0.9mm; Value: 100pF
D33 = CMP-0028951-2: Diode, Schottky, 60 V, 0.5 A, SOD-123; Manufacturer: Diodes Inc.; TJmax_C: 150°C; SizeArea_mm2: 6.545; SizeZ_mm: 1.35; Value2: 0.5V; SizeAreaWB_mm2: 13.095; Value: 60V; Green_REACh: Incomplete; Value1: 0.5A; SizeX_mm: 3.85; Vf_V: 500mV; AEC Qualified: N; AEC Category: Q101; SizeY_mm: 1.7; Green_Lifecycle: Not Set; Io_A: 500mA
H13 H14 = CMP-0003617-1: as H1 on sheet TIDA-011012-LV Power Conversion
J28 J29 = CMP-0122568-1: Mini-Latch™ Wire-to-Board Header, Vertical, with Friction Ramp, 3 Circuits, Gold (Au) Plating; Manufacturer: Molex; ContactFinish: Gold,Nickel; Current_A: 3A; Row_Count: 1; Voltage_V: 250V; AEC Qualified: No; Conn Gender: Male; DUT-Pitch_mm: 2.5mm; SizeZ_mm: 12.1mm
Q2 = CMP-0089138-1: MOSFET N-CH 30V 5.8A SOT23; Manufacturer: Diodes; Reverse Recovery Charge: 1.9nC; Pulse Drain Current: 30A; Power_W: 0.72W; Turn Off Delay Time: 13.9ns; Rthja Max: 171°C/W; TJmax_C: +150°C; Typ Forward Diode Voltage: 0.7V; ChMode: False; SizeZ_mm: 1.1mm; Vgs_V: 12V; AEC Qualified: No; Input Capacitace At Vds: 570pF @ 15V; Threshold Vgs Max: 1.4V; Threshold Vgs Min: 0.6V; VdsMax_V: 1.2V; Number Of Channels: 1; Rdson45_ohm: 21m; Reverse Recovery Time: 7.8ns; QgTyp_nC: 13.3nC @ 10V; Standoff Height: 0.013mm; Turn On Delay Time: 1.5ns
R186 R189 = CMP-0025880-3: RES, 47, 5%, 0.1 W, AEC-Q200 Grade 0, 0603; Manufacturer: Panasonic; Power_W: 100mW; TempCo: 200 ppm/C; Value_Code: 47R0; U/M: EA; Value: 47; EIA_Code: E24; SizeX_mm: 1.6; SizeY_mm: 0.8; SizeZ_mm: 1; Value2: 0.1W; SizeArea_mm2: 1.28; AEC Qualified: Y; AEC Grade: 0; AEC Category: Q200
R187 = CMP-0023921-2: RES, 200, 0.1%, 0.1 W, 0603; Manufacturer: Yageo America; Power_W: 100mW; TempCo: 25 ppm/C; Value_Code: 200R; U/M: EA; Value: 200; EIA_Code: E192; SizeX_mm: 1.6; SizeY_mm: 0.8; SizeZ_mm: 1; Value2: 0.1W; SizeArea_mm2: 1.28; VDC_V: 75V; AEC Category: Q200
R188 = CMP-0098286-1: 10 kOhms ±5% 0.1W, 1/10W Chip Resistor 0603 (1608 Metric) Thick Film; Manufacturer: Vishay; AEC Qualified: No; Power_W: 100mW; SizeZ_mm: 0.55mm; TempCo: 200ppm/°C; VDC_V: 75V; Value: 10k
R190 = CMP-0023235-5: RES, 680, 1%, 0.1 W, 0603; Manufacturer: Yageo; Power_W: 100mW; TempCo: 100 ppm/C; Value_Code: 680R; Value: 680; SizeX_mm: 1.6; SizeY_mm: 0.8; SizeZ_mm: 1; Value2: 0.1W; SizeArea_mm2: 1.28; AEC Qualified: N; VDC_V: 75V; AEC Category: Q200; SizeAreaWB_mm2: 4.68
R218 = CMP-0097467-1: 0 Ohms Jumper 0.125W, 1/8W Chip Resistor 0603 (1608 Metric) Automotive AEC-Q200 Thick Film; Manufacturer: Panasonic; VDC_V: 75V; Power_W: 125mW; AEC Qualified: Yes; SizeZ_mm: 0.55mm; AEC Grade: Grade 0
U14 U15 = CMP-0122473-1: Automotive ±1.5°C, 3-kVRMS Isolated Temperature Sensor With Analog Output With < 2 Seconds Response Time and 500VRMS Working Voltage; Manufacturer: Texas Instruments; SizeZ_mm: 1.75mm; AEC Qualified: Yes; AEC Grade: Grade 0; Max Supply Voltage: 5.5V; Min Supply Voltage: 2.3V; Operating Supply Current: 10uA; Sensor Output: Analog Voltage; Standoff Height: 0.11mm; TaMax_C: +150°C; TaMin_C: -40°C; TJmax_C: +155°C
U16 = CMP-0081550-1: Low-Power, Rail-to-Rail In and Out, 1-MHz Operational Amplifier, DBV0005A (SOT-23-5); Alternate PartNumber: TLV9001IDBVT; Alternate Manufacturer: Texas Instruments; SizeAreaWB_mm2: 14.82; SizeZ_mm: 1.45; SizeX_mm: 2.8; SizeY_mm: 2.9; SizeArea_mm2: 8.12; CompType: IC; AEC Qualified: N; AEC Category: Q200
U29 = CMP-0051712-2: Single Power Supply BUFFER Logic Level Shifter (no enable), DBV0005A, LARGE T&R; Manufacturer: Texas Instruments; F @ Nom Voltage(Max)(Mhz): 50; Logic: True; ICC @ Nom Voltage(Max)(mA): 0.01; Output Drive (IOL/IOH)(Max)(mA): 8/-8; Special Features: 1.8V to 3.3V Up Translation,3.3V to 1.8V Down Translation,5V Input Tolerant; VCC(Max)(V): 5.5; Technology Family: LV1T; tpd @ Nom Voltage(Max)(ns): 14.5,9.5,8.0,6.5; Rating: Catalog; Sub-Family: Non-Inverting Buffer/Driver; Input Type: TTL; VCC(Min)(V): 1.6; 3-State Output: Yes; Bits(#): 1; Voltage(Nom)(V): 1.8,2.5,3.3,5.5; Output Type: CMOS; AEC Category: Q200; AEC Qualified: N; CompType: IC; SizeAreaWB_mm2: 14.82; SizeArea_mm2: 8.12; SizeX_mm: 2.8; SizeY_mm: 2.9; SizeZ_mm: 1.45

## Sheet TIDA-011012-LV Optical Interface.SchDoc
size 431 x 279 mm; Date: Not shown in title block; ApprovedBy: Not shown in title block; CheckedBy: Not shown in title block; Author: Not shown in title block; CompanyName: Not shown in title block; Engineer: Not shown in title block; Organization: Not shown in title block; Address1: Not shown in title block; Address2: Not shown in title block; Address3: Not shown in title block; Address4: Not shown in title block; DocumentNumber: 8; Revision: Use project parameter SCH_Rev; SheetNumber: 8; SheetTotal: 10; PageSetup: Record=PageOptions¦CenterHorizontal=True¦CenterVertical=True¦PrintScale=1.00¦XCorrection=1.00¦YCorrection=1.00¦PrintKind=0¦BorderSize=5000000¦LeftOffset=0¦BottomOffset=0¦Orientation=2¦PaperLength=1000¦PaperWidth=1000¦Scale=100¦PaperSource=15¦PrintQuality=600¦MediaType=1¦DitherType=10¦PaperKind=Letter¦PrintScaleMode=1
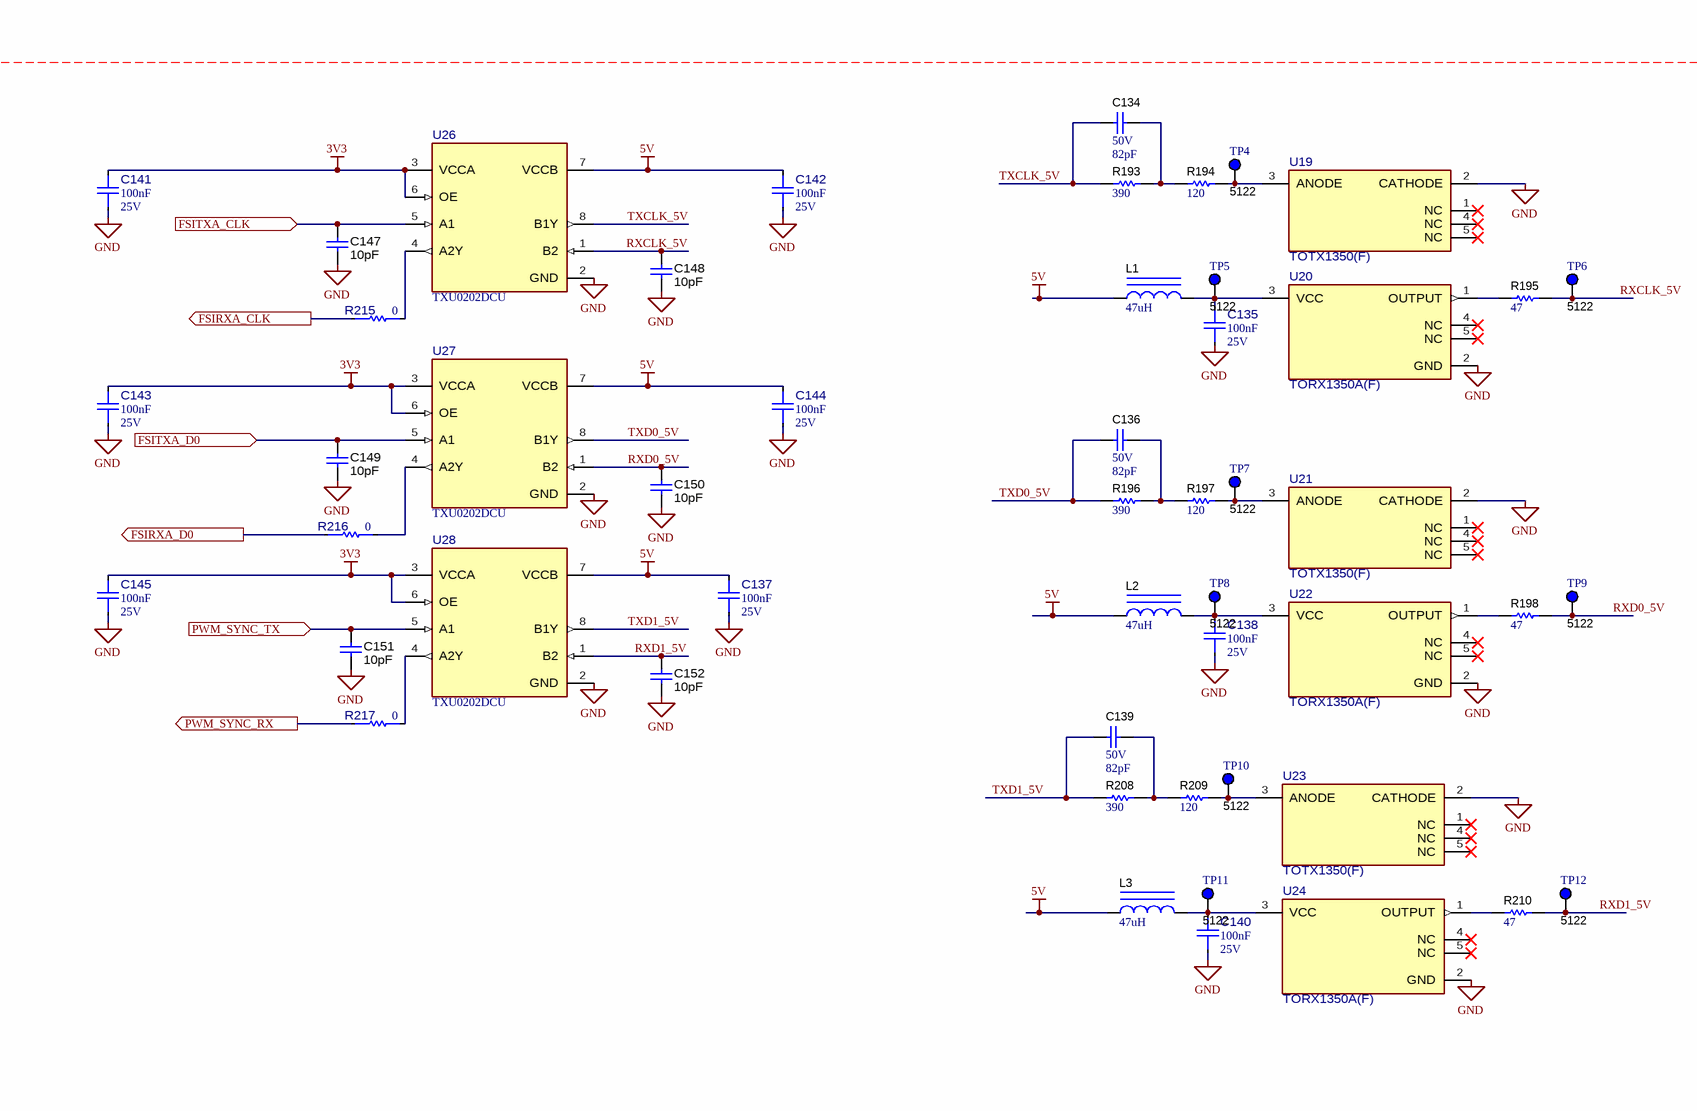
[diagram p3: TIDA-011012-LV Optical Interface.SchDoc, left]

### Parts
C134  VDC_V: 50V  ValueDisplayed: 82pF  [0603]  (hidden comment: C0603C820K5GACTU)
C135  Cap_F: 100nF  VDC_V: 25V  [FP-GMC10X7R104K25NT_0603-MFG]  (hidden comment: GMC10X7R104K25NT)
C136  VDC_V: 50V  ValueDisplayed: 82pF  [0603]  (hidden comment: C0603C820K5GACTU)
C137  Cap_F: 100nF  VDC_V: 25V  [FP-GMC10X7R104K25NT_0603-MFG]  (hidden comment: GMC10X7R104K25NT)
C138  Cap_F: 100nF  VDC_V: 25V  [FP-GMC10X7R104K25NT_0603-MFG]  (hidden comment: GMC10X7R104K25NT)
C139  VDC_V: 50V  ValueDisplayed: 82pF  [0603]  (hidden comment: C0603C820K5GACTU)
C140  Cap_F: 100nF  VDC_V: 25V  [FP-GMC10X7R104K25NT_0603-MFG]  (hidden comment: GMC10X7R104K25NT)
C141  Cap_F: 100nF  VDC_V: 25V  [FP-GMC10X7R104K25NT_0603-MFG]  (hidden comment: GMC10X7R104K25NT)
C142  Cap_F: 100nF  VDC_V: 25V  [FP-GMC10X7R104K25NT_0603-MFG]  (hidden comment: GMC10X7R104K25NT)
C143  Cap_F: 100nF  VDC_V: 25V  [FP-GMC10X7R104K25NT_0603-MFG]  (hidden comment: GMC10X7R104K25NT)
C144  Cap_F: 100nF  VDC_V: 25V  [FP-GMC10X7R104K25NT_0603-MFG]  (hidden comment: GMC10X7R104K25NT)
C145  Cap_F: 100nF  VDC_V: 25V  [FP-GMC10X7R104K25NT_0603-MFG]  (hidden comment: GMC10X7R104K25NT)
C147  Cap_F: 10pF  [0603]  (hidden comment: 0603ZC100KAT2A)
C148  Cap_F: 10pF  [0603]  (hidden comment: 0603ZC100KAT2A)
C149  Cap_F: 10pF  [0603]  (hidden comment: 0603ZC100KAT2A)
C150  Cap_F: 10pF  [0603]  (hidden comment: 0603ZC100KAT2A)
C151  Cap_F: 10pF  [0603]  (hidden comment: 0603ZC100KAT2A)
C152  Cap_F: 10pF  [0603]  (hidden comment: 0603ZC100KAT2A)
L1  ValueDisplayed: 47uH  [NLCV25]  (hidden comment: NLFV25T-470K-PF)
L2  ValueDisplayed: 47uH  [NLCV25]  (hidden comment: NLFV25T-470K-PF)
L3  ValueDisplayed: 47uH  [NLCV25]  (hidden comment: NLFV25T-470K-PF)
R193  ValueDisplayed: 390  [0603]  (hidden comment: RC0603FR-07390RL)
R194  ValueDisplayed: 120  [0603]  (hidden comment: RC0603FR-07120RL)
R195  ValueDisplayed: 47  [0603]  (hidden comment: CRCW060347R0JNEA)
R196  ValueDisplayed: 390  [0603]  (hidden comment: RC0603FR-07390RL)
R197  ValueDisplayed: 120  [0603]  (hidden comment: RC0603FR-07120RL)
R198  ValueDisplayed: 47  [0603]  (hidden comment: CRCW060347R0JNEA)
R208  ValueDisplayed: 390  [0603]  (hidden comment: RC0603FR-07390RL)
R209  ValueDisplayed: 120  [0603]  (hidden comment: RC0603FR-07120RL)
R210  ValueDisplayed: 47  [0603]  (hidden comment: CRCW060347R0JNEA)
R215  value 0  [FP-ERJ-H3G0R00V_0603-MFG]  (hidden comment: ERJ-H3G0R00V)
R216  value 0  [FP-ERJ-H3G0R00V_0603-MFG]  (hidden comment: ERJ-H3G0R00V)
R217  value 0  [FP-ERJ-H3G0R00V_0603-MFG]  (hidden comment: ERJ-H3G0R00V)
TP4  5122  [Keystone5122]
TP5  5122  [Keystone5122]
TP6  5122  [Keystone5122]
TP7  5122  [Keystone5122]
TP8  5122  [Keystone5122]
TP9  5122  [Keystone5122]
TP10  5122  [Keystone5122]
TP11  5122  [Keystone5122]
TP12  5122  [Keystone5122]
U19  TOTX1350(F)  [FP-TOTX1350(F)_REC_OPT_PTH-MFG]
U20  TORX1350A(F)  [FP-TORX1350A(F)_OPTIC_RECIEVER_13MM0_13MM5-MFG]
U21  TOTX1350(F)  [FP-TOTX1350(F)_REC_OPT_PTH-MFG]
U22  TORX1350A(F)  [FP-TORX1350A(F)_OPTIC_RECIEVER_13MM0_13MM5-MFG]
U23  TOTX1350(F)  [FP-TOTX1350(F)_REC_OPT_PTH-MFG]
U24  TORX1350A(F)  [FP-TORX1350A(F)_OPTIC_RECIEVER_13MM0_13MM5-MFG]
U26  TXU0202DCU  [DCU0008A-MFG]
U27  TXU0202DCU  [DCU0008A-MFG]
U28  TXU0202DCU  [DCU0008A-MFG]

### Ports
FSIRXA_CLK (out), FSIRXA_D0 (out), FSITXA_CLK (in), FSITXA_D0 (in), PWM_SYNC_RX (out), PWM_SYNC_TX (in)

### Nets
3V3: C141.2 C143.2 C145.2 U26.3(VCCA) U26.6(OE) U27.3(VCCA) U27.6(OE) U28.3(VCCA) U28.6(OE)
5V: C137.2 C142.2 C144.2 L1.1 L2.1 L3.1 U26.7(VCCB) U27.7(VCCB) U28.7(VCCB)
GND: C135.1 C137.1 C138.1 C140.1 C141.1 C142.1 C143.1 C144.1 C145.1 C147.2 C148.2 C149.2 C150.2 C151.2 C152.2 U19.2(CATHODE) U20.2(GND) U21.2(CATHODE) U22.2(GND) U23.2(CATHODE) U24.2(GND) U26.2(GND) U27.2(GND) U28.2(GND)
FSIRXA_CLK: R215.1 ; port FSIRXA_CLK
FSIRXA_D0: R216.1 ; port FSIRXA_D0
FSITXA_CLK: C147.1 U26.5(A1) ; port FSITXA_CLK
FSITXA_D0: C149.1 U27.5(A1) ; port FSITXA_D0
PWM_SYNC_RX: R217.1 ; port PWM_SYNC_RX
PWM_SYNC_TX: C151.1 U28.5(A1) ; port PWM_SYNC_TX
RXCLK_5V: C148.1 R195.2 TP6.1 U26.1(B2)
RXD0_5V: C150.1 R198.2 TP9.1 U27.1(B2)
RXD1_5V: C152.1 R210.2 TP12.1 U28.1(B2)
TXCLK_5V: C134.2 R193.1 U26.8(B1Y)
TXD0_5V: C136.2 R196.1 U27.8(B1Y)
TXD1_5V: C139.2 R208.1 U28.8(B1Y)
NetC134_1: C134.1 R193.2 R194.1
NetC135_2: C135.2 L1.2 TP5.1 U20.3(VCC)
NetC136_1: C136.1 R196.2 R197.1
NetC138_2: C138.2 L2.2 TP8.1 U22.3(VCC)
NetC139_1: C139.1 R208.2 R209.1
NetC140_2: C140.2 L3.2 TP11.1 U24.3(VCC)
NetR194_2: R194.2 TP4.1 U19.3(ANODE)
NetR195_1: R195.1 U20.1(OUTPUT)
NetR197_2: R197.2 TP7.1 U21.3(ANODE)
NetR198_1: R198.1 U22.1(OUTPUT)
NetR209_2: R209.2 TP10.1 U23.3(ANODE)
NetR210_1: R210.1 U24.1(OUTPUT)
NetR215_2: R215.2 U26.4(A2Y)
NetR216_2: R216.2 U27.4(A2Y)
NetR217_2: R217.2 U28.4(A2Y)

Not connected (* = marked no-connect by the designer): U19 1(NC)* 4(NC)* 5(NC)*; U20 4(NC)* 5(NC)*; U21 1(NC)* 4(NC)* 5(NC)*; U22 4(NC)* 5(NC)*; U23 1(NC)* 4(NC)* 5(NC)*; U24 4(NC)* 5(NC)*

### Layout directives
net class HVM: 3V3, 5V, GND, RXCLK_5V, RXD0_5V, RXD1_5V, TXCLK_5V, TXD0_5V, TXD1_5V

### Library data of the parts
C134 C136 C139 = CMP-0006970-4: CAP, CERM, 82 pF, 50 V, +/- 10%, C0G/NP0, 0603; Manufacturer: Kemet; TaMin_C: -55°C; Polarized: N; SizeAreaWB_mm2: 4.68; Value1: Unknown; U/M: EA; Value: 82pF; TaMax_C: 125°C; SizeZ_mm: 1; SizeX_mm: 1.6; SizeY_mm: 0.8; SizeArea_mm2: 1.28; AEC Category: Q200
C135 C137 C138 C140-C145 = CMP-0094950-1: 0.1 µF ±10% 25V Ceramic Capacitor X7R 0603 (1608 Metric); Manufacturer: CAL-CHIP ELECTRONICS; AEC Qualified: No; SizeZ_mm: 1mm; Value: 100nF; ValueDisplayed: 0.1uF; TempCo: 30ppm/°C
C147-C152 = CMP-0006811-4: CAP, CERM, 10 pF, 10 V, +/- 10%, X7R, 0603; Manufacturer: AVX; TaMin_C: -55°C; Polarized: N; SizeAreaWB_mm2: 4.68; Value1: Unknown; U/M: EA; Value: 10pF; TaMax_C: 125°C; SizeZ_mm: 1; SizeX_mm: 1.6; SizeY_mm: 0.8; Value2: 10V; SizeArea_mm2: 1.28; AEC Category: Q200
L1-L3 = CMP-0062508-2: Inductor, Shielded, Ferrite, 47 uH, 0.06 A, 1.7 ohm, SMD; Manufacturer: TDK; Isat: 0.06A @ 10% inductance drop; Irms: 0.06A @ 20C rise; Green_Lifecycle: Active; SizeAreaWB_mm2: 9.8; DCR_ohm: 1.7; Green_REACh: Passed; Value1: 1.7 ohm; Value: 47uH; Imax_A: 60mA; SizeZ_mm: 2; SizeX_mm: 2.5; SizeY_mm: 1.8; Value2: 0.06A; SizeArea_mm2: 4.5; Ind_H: 47µH; AEC Category: Q200
R193 R196 R208 = CMP-0023069-5: RES, 390, 1%, 0.1 W, 0603; Manufacturer: Yageo; Power_W: 100mW; TempCo: 100 ppm/C; Value_Code: 390R; Value: 390; SizeX_mm: 1.6; SizeY_mm: 0.8; SizeZ_mm: 1; Value2: 0.1W; SizeArea_mm2: 1.28; AEC Qualified: N; VDC_V: 75V; AEC Category: Q200; SizeAreaWB_mm2: 4.68
R194 R197 R209 = CMP-0022769-5: RES, 120, 1%, 0.1 W, 0603; Manufacturer: Yageo; Power_W: 100mW; TempCo: 100 ppm/C; Value_Code: 120R; Value: 120; SizeX_mm: 1.6; SizeY_mm: 0.8; SizeZ_mm: 1; Value2: 0.1W; SizeArea_mm2: 1.28; AEC Qualified: N; VDC_V: 75V; AEC Category: Q200; SizeAreaWB_mm2: 4.68
R195 R198 R210 = CMP-0025815-4: RES, 47, 5%, 0.1 W, AEC-Q200 Grade 0, 0603; Manufacturer: Vishay-Dale; Power_W: 100mW; TempCo: 200 ppm/C; Value_Code: 47R0; Value: 47; EIA_Code: E24; SizeX_mm: 1.6; SizeY_mm: 0.8; SizeZ_mm: 1; Value2: 0.1W; SizeArea_mm2: 1.28; AEC Qualified: Y; VDC_V: 75V; AEC Category: Q200; AEC Grade: 0
R215-R217 = CMP-0097467-1: as R218 on sheet TIDA-011012-LV Fans and Temp Sense
TP4-TP12 = CMP-0055155-2: as TP13 on sheet TIDA-011012-LV Power Conversion
U19 U21 U23 = CMP-0092228-1: Fiber Optic Transmitter 650nm 1.8V TOSLINK; Manufacturer: Toshiba; SizeZ_mm: 8.8mm; Vr_V: 5V; Min Supply Voltage: 4.75V; AEC Qualified: No; Max Supply Voltage: 5.25V; Vf_V: 2V; Standoff Height: 0.1mm; Forward Current: 6mA
U20 U22 U24 = CMP-0092227-1: Fiber Optic Receiver General Purpose 10Mbps -27dBm 4.75V ~ 5.25V; Manufacturer: Toshiba; Sensing Distance: 0.2-100m; SizeZ_mm: 8.8mm; Standoff Height: 0.1mm; AEC Qualified: No
U26-U28 = CMP-0093827-1: Single-Bit Fixed Direction Voltage-Level Translator with Schmitt-Trigger Inputs and 3-State Outputs; Manufacturer: Texas Instruments; SizeZ_mm: 0.9mm; Standoff Height: 0mm; V A Max: 5.5V; Number Of Inputs: 1; V B Min: 1.1V; PositionCount: 2; Logic Function Desc: Non-Inverting; AEC Qualified: No; Data Rate: 200Mbits/s; Propagation Delay: 8ns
